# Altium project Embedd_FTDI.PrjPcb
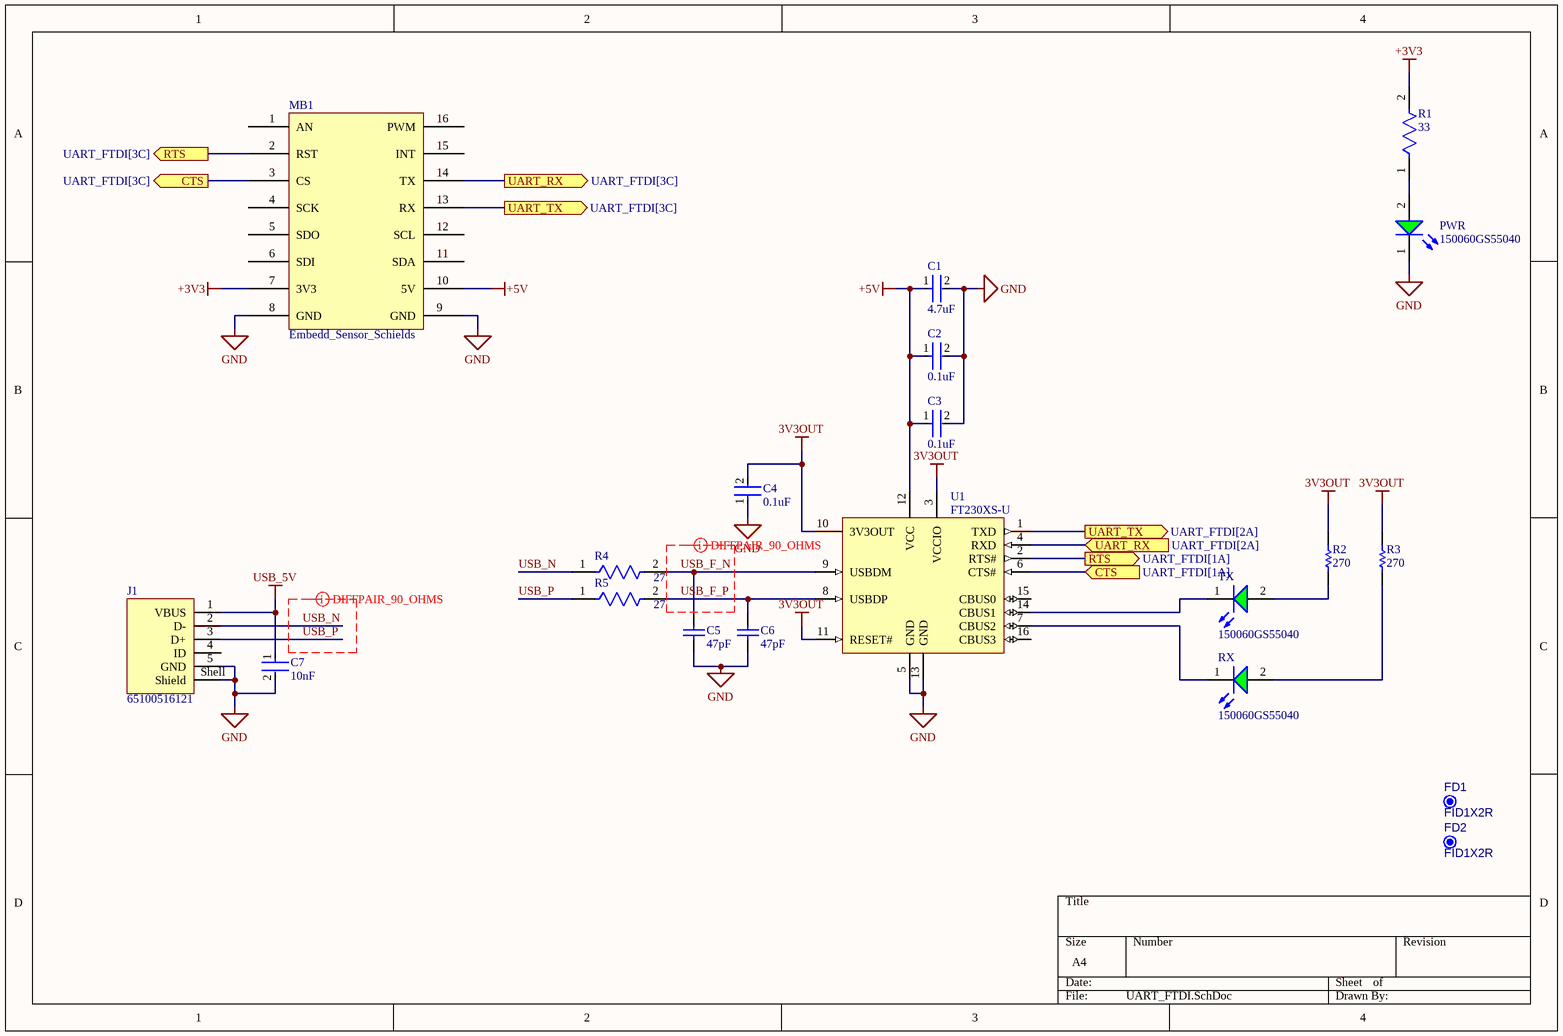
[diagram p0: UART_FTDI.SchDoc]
1 sheet, 20 parts. Net scope: flat (ports and power ports of the same name join across sheets).
Board file: UART_PCB_FTDI.PcbDoc

## Sheet UART_FTDI.SchDoc
size A4; SheetNumber: 1; SheetTotal: 1

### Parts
C1  4.7uF  [FP-CL10-IPC_C]
C2  0.1uF  [FP-CC0603-DA-IPC_A]
C3  0.1uF  [FP-CC0603-DA-IPC_A]
C4  0.1uF  [FP-CC0603-DA-IPC_A]
C5  47pF  [WCAP-CSGP_0603_L1.6W0.8H0.8_Reflow]
C6  47pF  [WCAP-CSGP_0603_L1.6W0.8H0.8_Reflow]
C7  10nF  [FP-C0603C-CF-MFG]
FD1  FID1X2R  [FID1X2R]  (no BOM)
FD2  FID1X2R  [FID1X2R]  (no BOM)
J1  65100516121  [65100516121]
MB1  Embedd_Sensor_Schields  [Embedd_add_on_board_25,4 x 30,58]
PWR  150060GS55040  [WL-SMCD_0603]
R1  33  [FP-CRCW0603-e3-IPC_A]
R2  270  [RESC1608X55X30ML15T15]
R3  270  [RESC1608X55X30ML15T15]
R4  27  [FP-ESR03-IPC_B]
R5  27  [FP-ESR03-IPC_B]
RX  150060GS55040  [WL-SMCD_0603]
TX  150060GS55040  [WL-SMCD_0603]
U1  FT230XS-U  [SSOP-16_L]

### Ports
CTS (in, see UART_FTDI[1A]), CTS (out, see UART_FTDI[3C]), RTS (out, see UART_FTDI[1A]), RTS (out, see UART_FTDI[3C]), UART_RX (in, see UART_FTDI[2A]), UART_RX (out, see UART_FTDI[3C]), UART_TX (out, see UART_FTDI[2A]), UART_TX (out, see UART_FTDI[3C])

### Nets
3V3OUT: C4.2 R2.2 R3.2 U1.3(VCCIO) U1.10(3V3OUT) U1.11(RESET#)
+3V3: MB1.7(3V3) R1.2
+5V: C1.1 C2.1 C3.1 MB1.10(5V) U1.12(VCC)
GND: C1.2 C2.2 C3.2 C4.1 C5.2 C6.2 C7.2 J1.5(GND) J1.Shell(Shield) MB1.8(GND) MB1.9(GND) PWR.1(K) U1.5(GND) U1.13(GND)
USB_5V: C7.1 J1.1(VBUS)
USB_F_N: C5.1 R4.2 U1.9(USBDM)
USB_F_P: C6.1 R5.2 U1.8(USBDP)
USB_N: J1.2(D-) R4.1
USB_P: J1.3(D+) R5.1
NetMB1_2: MB1.2(RST) U1.2(RTS#) ; port RTS
NetMB1_3: MB1.3(CS) U1.6(CTS#) ; port CTS
NetMB1_13: MB1.13(RX) U1.1(TXD) ; port UART_TX
NetMB1_14: MB1.14(TX) U1.4(RXD) ; port UART_RX
NetPWR_2: PWR.2(A) R1.1
NetR2_1: R2.1 TX.2(A)
NetR3_1: R3.1 RX.2(A)
NetRX_1: RX.1(K) U1.7(CBUS2)
NetTX_1: TX.1(K) U1.14(CBUS1)

Not connected (* = marked no-connect by the designer): J1 4(ID); MB1 1(AN) 4(SCK) 5(SDO) 6(SDI) 11(SDA) 12(SCL) 15(INT) 16(PWM); U1 15(CBUS0) 16(CBUS3)

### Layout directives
differential pair: USB_F_N, USB_F_P, USB_N, USB_P

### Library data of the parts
C1 = CMP-13271-003017-1: Cap Ceramic 4.7uF 10V X5R ±10% Pad SMD 0603 +85°C T/R
C2-C4 = CMP-03422-001490-1: CAP CER 0.1UF 50V X7R 0603; Capacitance: 100nF; Tolerance: 5%
C5 C6 = CMP-03913-65419532-1: 885012006006 Ceramic Capacitor 47pF, 10VDC, 0603, ±5 %; Tolerance: 5%; Insulation Resistance: 10GΩ; Voltage Rating (DC): 10V
C7 = CMP-2006-03036-2: CAP CER 10000PF 100V X7R 0603; Manufacturer: KEMET; Manufacturer Part Number: C0603C103K1RACTU; Temperature Coefficient: 30ppm/°C; Capacitance: 10,000 pF; Automotive Grade: Grade 1; Value: 10,000 pF; Tolerance: 0.1; Material: Ceramic
FD1 FD2 = CMP-00028-00005-4: Fiducial - Round 1x2mm
J1 = CMP-2000-05576-3: NexarPartId: 21041531; USB Standard: USB 2.0; Number of Positions: 5; Voltage Rating (DC): 30V; Number of Ports: 1; Gender: Receptacle; Current Rating: 1A; Connector Type: Socket, USB; Contact Resistance: 20mΩ; Insulation Resistance: 1GΩ
MB1 = CMP-00030-00005-3: Footprint for sensor shields
PWR RX TX = CMP-03913-90235563-2: 150060GS55040 WL-SMCD SMT Mono-color Chip LED Diffused; Forward Voltage: 3.2V; Forward Current: 60mA; Luminous Intensity: 430mcd; Peak Wavelength: 520nm; Viewing Angle: 140°; Wavelength: 525nm; Max Reverse Voltage (DC): 5V
R1 = CMP-2000-03250-2: RES Thick Film, 33Ω, 1%, 0.1W, 100ppm/°C, 0603; Voltage Rating: 75V; Max Power Dissipation: 100mW; Resistance: 33R
R2 R3 = CMP-2000-00758-1: Manufacturer: Panasonic; Part Number: ERJ-3GEYJ271V
R4 R5 = CMP-08839-028859-1: 27Ω ±0.5% 0.25W 0603 Anti-Surge Chip Resistor AEC-Q200
U1 = CMP-0248-00025-2: USB to Basic UART Interface Chip, UHCI/OHCI/EHCI Compatible, USB 2.0 Compatible, -40 to +85 degC, 16-Pin SSOP, Pb-Free, Tube; Manufacturer: FTDI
